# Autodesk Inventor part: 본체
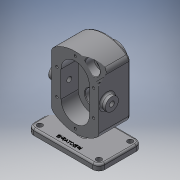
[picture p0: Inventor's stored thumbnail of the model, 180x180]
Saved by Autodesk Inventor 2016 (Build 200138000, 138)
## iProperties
Created: 2019-03
Part Number: 본체
Material: Generic
Document SubType Name: Modeling
Designer: MIRAE
Density: 1 g/cm^3
Appearance: Default
Author: MIRAE
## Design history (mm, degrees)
sketch "스케치1"
  geometry: L1 (40, 44.721)-(40, -44.721); L2 (0, -84)-(0, 84) reference; L3 (-40, 44.721)-(-40, -44.721); A1 r 60 centre (0, 0) between (40, 44.721) and (40, -44.721); 1 further point
  constraints: 4 end point, 4 point on circle, 2 vertical, 1 centre point, 1 coincident
  dimensions: "d0" = 120 diameter of A1; "d1" = 40 distance between parallel lines of L1 L2; "d2" = 40 distance between parallel lines of L2 L3
extrude "돌출1" new body sketch "스케치1" distance "d3" = 53; taper "d4" = 0 deg
fillet "모깎기1" dims "d5" = 10
sketch "스케치2"
  geometry: L1 (0, -22)-(0, 22); L2 (24, -22)-(24, 22); L3 (-24, 22)-(-24, -22); A1 r 24 centre (0, -22) between (-24, -22) and (24, -22); A2 r 24 centre (0, 22) between (24, 22) and (-24, 22); 1 further point
  constraints: 8 end point, 4 point on circle, 4 tangent, 2 centre point, 1 midpoint, 1 parallel, 1 vertical
  dimensions: "d6" = 22 distance of point (0, 0) L1.end; "d7" = 48 diameter of A2
extrude "돌출2" cut sketch "스케치2" distance "d8" = 29; taper "d9" = 0 deg
sketch "스케치3"
  geometry: 2 further points
  dimensions: "d10" = 22 vertical distance of point (0, 0) point (31, 22); "d11" = 31 horizontal distance of point (0, 0) point (31, 22)
hole "구멍1" sketch "스케치3" at (31, 22) diameter "d12" = 4.134; stored, may be unused: countersink angle "d16" = 90 deg, drill point angle "d18" = 118 deg; dims "d13" = 10, "d14" = 4, "d15" = 2, "d17" = 12
sketch "스케치4"
  geometry: L1 (18, -53)-(62, -53) reference; C1 r 11 at (40, -39); 1 further point
  constraints: 1 centre point, 1 vertical alignment
  dimensions: "d22" = 22 diameter of C1; "d23" = 14 distance from line of C1.centre L1
extrude "돌출3" join sketch "스케치4" distance "d24" = 8; taper "d25" = 0 deg
fillet "모깎기2" dims "d26" = 3
hole "구멍2" diameter "d29" = 8.376; stored, may be unused: countersink angle "d33" = 90 deg, drill point angle "d35" = 118 deg; dims "d27" = 10, "d28" = 10, "d30" = 100, "d31" = 4, "d32" = 2, "d34" = 27.3
feature "분할1"
sketch "스케치5"
  geometry: C1 r 19 at (0, -22); A1 r 24 centre (0, -22) between (-24, -22) and (24, -22) reference; 1 further point
  constraints: 1 centre point, 1 concentric
  dimensions: "d36" = 38 diameter of C1
extrude "돌출4" join sketch "스케치5" distance "d37" = 17; taper "d38" = 0 deg
hole "구멍3" diameter "d41" = 17; stored, may be unused: countersink angle "d45" = 90 deg, drill point angle "d47" = 118 deg; dims "d39" = 10, "d40" = 10, "d42" = 100, "d43" = 28, "d44" = 7.3, "d46" = 27.3
fillet "모깎기3" dims "d48" = 0.5
chamfer "모따기1" distance "d49" = 0.7; stored, may be unused: second distance "d50" = 2, angle "d51" = 30 deg
hole "구멍4" diameter "d54" = 25; stored, may be unused: countersink angle "d58" = 90 deg, drill point angle "d60" = 0 deg; dims "d55" = 100, "d56" = 28, "d57" = 7.3, "d59" = 15, "d72" = 10, "d73" = 10
hole "구멍5" diameter "d63" = 25; stored, may be unused: countersink angle "d67" = 90 deg, drill point angle "d69" = 0 deg; dims "d64" = 100, "d65" = 28, "d66" = 7.3, "d68" = 15, "d70" = 10, "d71" = 10
chamfer "모따기2" distance "d74" = 1; stored, may be unused: second distance "d75" = 2, angle "d76" = 30 deg
sketch "스케치7"
  geometry: L1 (0, -78)-(-73, -78); L2 (-73, -78)-(-73, -68); L3 (-73, -68)-(0, -68); L4 (0, -68)-(0, -78); 1 further point
  constraints: 8 end point, 2 parallel, 1 horizontal, 1 perpendicular, 1 vertical alignment
  dimensions: "d77" = 10 distance of L1.end L2.end; "d78" = 73 distance of L1.start L1.end; "d79" = 78 distance from line of L1 point (0, 0)
extrude "돌출5" join sketch "스케치7" stored distance "d80" = 120; taper "d81" = 0 deg
fillet "모깎기4" dims "d82" = 10
hole "구멍6" diameter "d85" = 9; stored, may be unused: countersink angle "d89" = 90 deg, drill point angle "d91" = 118 deg; dims "d83" = 10, "d84" = 10, "d86" = 100, "d87" = 28, "d88" = 7.3, "d90" = 15
hole "구멍7" diameter "d94" = 9; stored, may be unused: countersink angle "d98" = 90 deg, drill point angle "d100" = 118 deg; dims "d92" = 10, "d93" = 10, "d95" = 100, "d96" = 28, "d97" = 7.3, "d99" = 15
hole "구멍8" diameter "d103" = 9; stored, may be unused: countersink angle "d107" = 90 deg, drill point angle "d109" = 118 deg; dims "d101" = 10, "d102" = 10, "d104" = 100, "d105" = 28, "d106" = 7.3, "d108" = 15
hole "구멍9" diameter "d112" = 9; stored, may be unused: countersink angle "d116" = 90 deg, drill point angle "d118" = 118 deg; dims "d110" = 10, "d111" = 10, "d113" = 100, "d114" = 28, "d115" = 7.3, "d117" = 15
sketch "스케치8"
  geometry: L1 (56, 30)-(44, 30); L2 (44, 30)-(44, 73); L3 (44, 73)-(56, 73); L4 (56, 73)-(56, 30); L5 (56, 30)-(44, 73); L6 (44, 30)-(56, 73); 4 further points
  constraints: 12 end point, 4 midpoint, 2 parallel, 1 coincident, 1 horizontal, 1 perpendicular, 1 vertical alignment
  dimensions: "d119" = 12 distance of L2.end L3.end; "d120" = 43 distance of L1.end L2.end
extrude "돌출6" join sketch "스케치8" stored distance "d121" = 120; taper "d122" = 0 deg
fillet "모깎기5" dims "d123" = 3
fillet "모깎기6" dims "d124" = 3
fillet "모깎기7" dims "d125" = 3
sketch "스케치9"
  geometry: L1 (-47, -27)-(53, -27) reference; L2 (-57, 36)-(-57, -17) reference; 2 further points
  constraints: 1 other
  dimensions: "d126" = 10 distance from line of L1 point (3, -17); "d127" = 60 distance from line of L2 point (3, -17)
feature "엠보싱1" sketch "스케치9" dims "d0" = 120, "d1" = 40, "d2" = 40, "d128" = 0.5, "d129" = 0
feature "분할2"
node "솔리드1"
pattern_circular "원형 패턴1" dims angle "d20" = 180 deg
mirror "대칭1"
mirror "대칭2"
